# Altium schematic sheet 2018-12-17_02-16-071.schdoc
size 441 x 220 mm; SheetNumber: 1; SheetTotal: 1
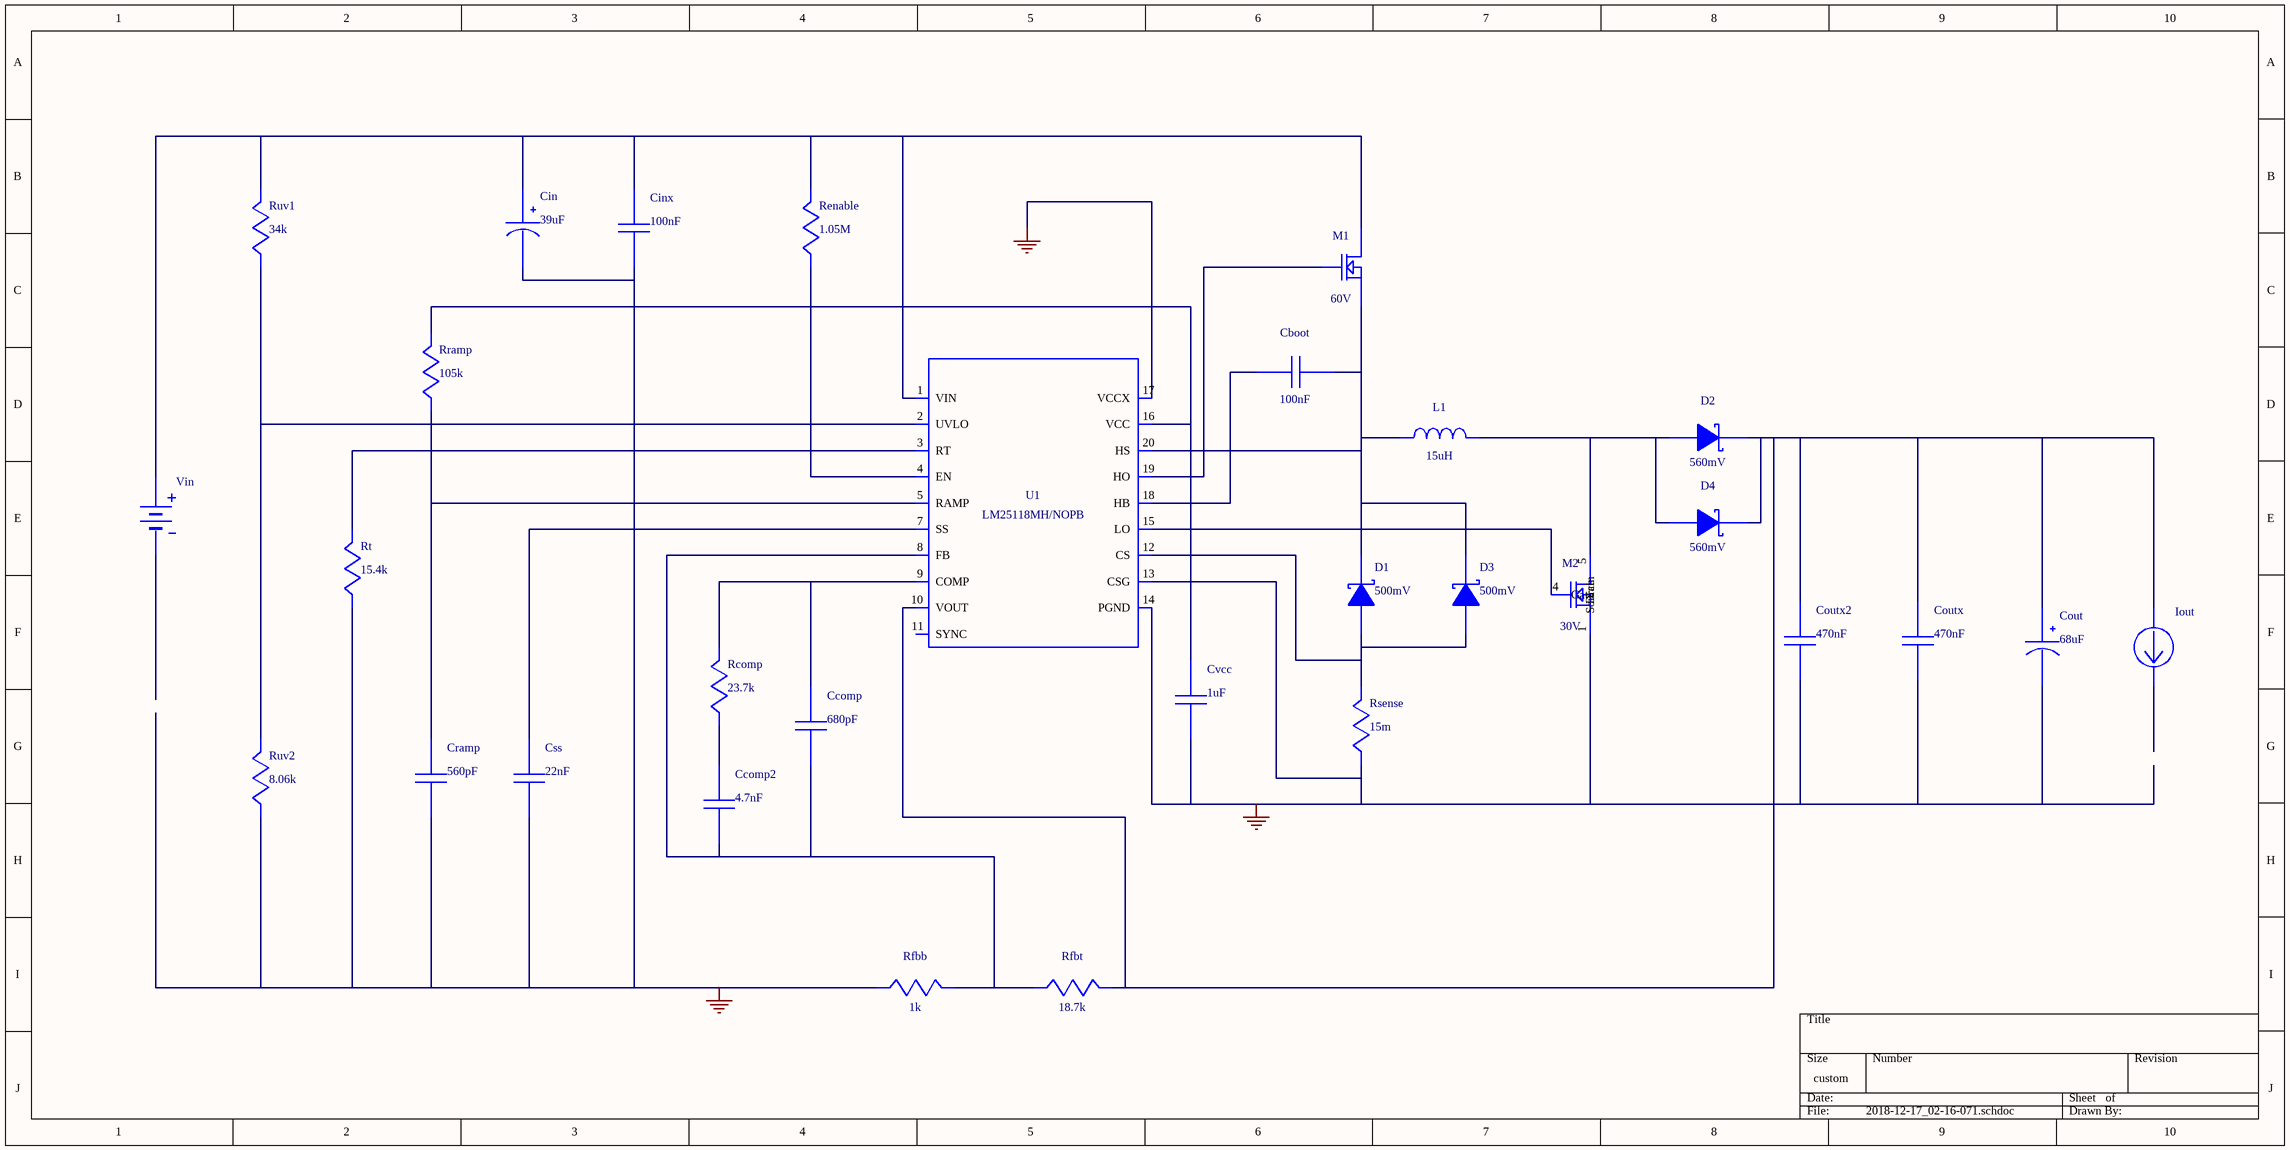
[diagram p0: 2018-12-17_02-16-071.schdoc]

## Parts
Cboot  value 100nF  (hidden comment: 08053C104JAZ2A)
Ccomp  value 680pF  (hidden comment: CGA2B2C0G1H681J050BA)
Ccomp2  value 4.7nF  (hidden comment: CGA4C2C0G1H472J060AA)
Cin  value 39uF  (hidden comment: 50SVPF39M)
Cinx  value 100nF  (hidden comment: C1005X7R1H104K050BB)
Cout  value 68uF  (hidden comment: 50SVPF68M)
Coutx  value 470nF  (hidden comment: C1608X7R1H474K080AC)
Coutx2  value 470nF  (hidden comment: C1608X7R1H474K080AC)
Cramp  value 560pF  (hidden comment: GRM1555C1H561JA01J)
Css  value 22nF  (hidden comment: CGA4J2C0G1H223J125AA)
Cvcc  value 1uF  (hidden comment: C1608X5R1H105K080AB)
D1  value 500mV  (hidden comment: B340A-13-F)
D2  value 560mV  (hidden comment: PDS760-13)
D3  value 500mV  (hidden comment: B340A-13-F)
D4  value 560mV  (hidden comment: PDS760-13)
Iout  WB_CURRENT_LOAD  (value not drawn)
L1  value 15uH  (hidden comment: XAL1010-153MEB)
M1  value 60V  (hidden comment: BSZ100N06LS3 G)
M2  value 30V  (hidden comment: CSD17308Q3)
Rcomp  value 23.7k  (hidden comment: RC0201FR-0723K7L)
Renable  value 1.05M  (hidden comment: CRCW04021M05FKED)
Rfbb  value 1k  (hidden comment: ERJ-6ENF1001V)
Rfbt  value 18.7k  (hidden comment: RC0201FR-0718K7L)
Rramp  value 105k  (hidden comment: RC0201FR-07105KL)
Rsense  value 15m  (hidden comment: PRL1632-R015-F-T1)
Rt  value 15.4k  (hidden comment: RC0201FR-0715K4L)
Ruv1  value 34k  (hidden comment: CRCW040234K0FKED)
Ruv2  value 8.06k  (hidden comment: CRCW04028K06FKED)
U1  LM25118MH/NOPB
Vin  WB_BATTERY  (value not drawn)

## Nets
0: Cin.2(-) Cinx.2 Cout.2(-) Coutx.2 Coutx2.2 Cramp.2 Css.2 Cvcc.2 M2.1(Source) M2.2(Source) M2.3(Source) Rfbb.2 Rsense.2 Rt.2 Ruv2.2 U1.6(AGND) U1.13(CSG) U1.14(PGND) U1.17(VCCX) U1.21(EXP-PAD)
NetCboot_1: Cboot.1 D1.1(K) D3.1(K) L1.2 M1.1(Source) M1.2(Source) M1.3(Source) U1.20(HS)
NetCboot_2: Cboot.2 U1.18(HB)
NetCcomp2_1: Ccomp2.1 Rcomp.2
NetCcomp_1: Ccomp.1 Rcomp.1 U1.9(COMP)
NetCcomp_2: Ccomp.2 Ccomp2.2 Rfbb.1 Rfbt.2 U1.8(FB)
NetCin_1: Cin.1(+) Cinx.1 M1.5(Drain) M1.6(Drain) M1.7(Drain) M1.8(Drain) M1.9(Drain) Renable.1 Ruv1.1 U1.1(VIN) Vin.1(+)
NetCout_1: Cout.1(+) Coutx.1 Coutx2.1 D2.2(K) D4.2(K) Iout.1(+) Rfbt.1 U1.10(VOUT)
NetCramp_1: Cramp.1 Rramp.2 U1.5(RAMP)
NetCss_1: Css.1 U1.7(SS)
NetCvcc_1: Cvcc.1 Rramp.1 U1.16(VCC)
NetD1_2: D1.2(A) D3.2(A) Rsense.1 U1.12(CS)
NetD2_1: D2.1(A) D4.1(A) L1.1 M2.5(Drain) M2.6(Drain) M2.7(Drain) M2.8(Drain) M2.9(Drain)
NetM1_4: M1.4(Gate) U1.19(HO)
NetM2_4: M2.4(Gate) U1.15(LO)
NetRenable_2: Renable.2 U1.4(EN)
NetRt_1: Rt.1 U1.3(RT)
NetRuv1_2: Ruv1.2 Ruv2.1 U1.2(UVLO)

Not connected (* = marked no-connect by the designer): Iout 2(-); U1 11(SYNC); Vin 2(-)

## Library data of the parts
Cboot = 08053C104JAZ2A: Manufacturer Name: AVX
Ccomp = CGA2B2C0G1H681J050BA: CGA2B2C0G1H681J0; Manufacturer Name: TDK
Ccomp2 = CGA4C2C0G1H472J060AA: CGA4C2C0G1H472J0; Manufacturer Name: TDK
Cin = 50SVPF39M: Manufacturer Name: Panasonic
Cinx = C1005X7R1H104K050BB: C1005X7R1H104K05; Manufacturer Name: TDK
Cout = 50SVPF68M: Manufacturer Name: Panasonic
Coutx Coutx2 = C1608X7R1H474K080AC: C1608X7R1H474K08; Manufacturer Name: TDK
Cramp = GRM1555C1H561JA01J: GRM1555C1H561JA0; Manufacturer Name: MuRata
Css = CGA4J2C0G1H223J125AA: CGA4J2C0G1H223J1; Manufacturer Name: TDK
Cvcc = C1608X5R1H105K080AB: C1608X5R1H105K08; Manufacturer Name: TDK
D1 D3 = B340A-13-F: Manufacturer Name: Diodes Inc.
D2 D4 = PDS760-13: Manufacturer Name: Diodes Inc.
L1 = XAL1010-153MEB: Manufacturer Name: Coilcraft
M1 = BSZ100N06LS3 G: Manufacturer Name: Infineon Technologies
M2 = CSD17308Q3: Manufacturer Name: Texas Instruments
Rcomp = RC0201FR-0723K7L: Manufacturer Name: Yageo
Renable = CRCW04021M05FKED: Manufacturer Name: Vishay-Dale
Rfbb = ERJ-6ENF1001V: Manufacturer Name: Panasonic
Rfbt = RC0201FR-0718K7L: Manufacturer Name: Yageo
Rramp = RC0201FR-07105KL: Manufacturer Name: Yageo
Rsense = PRL1632-R015-F-T1: PRL1632-R015-F-T; Manufacturer Name: Susumu Co Ltd
Rt = RC0201FR-0715K4L: Manufacturer Name: Yageo
Ruv1 = CRCW040234K0FKED: Manufacturer Name: Vishay-Dale
Ruv2 = CRCW04028K06FKED: Manufacturer Name: Vishay-Dale
U1 = LM25118MH/NOPB: Manufacturer Name: Texas Instruments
